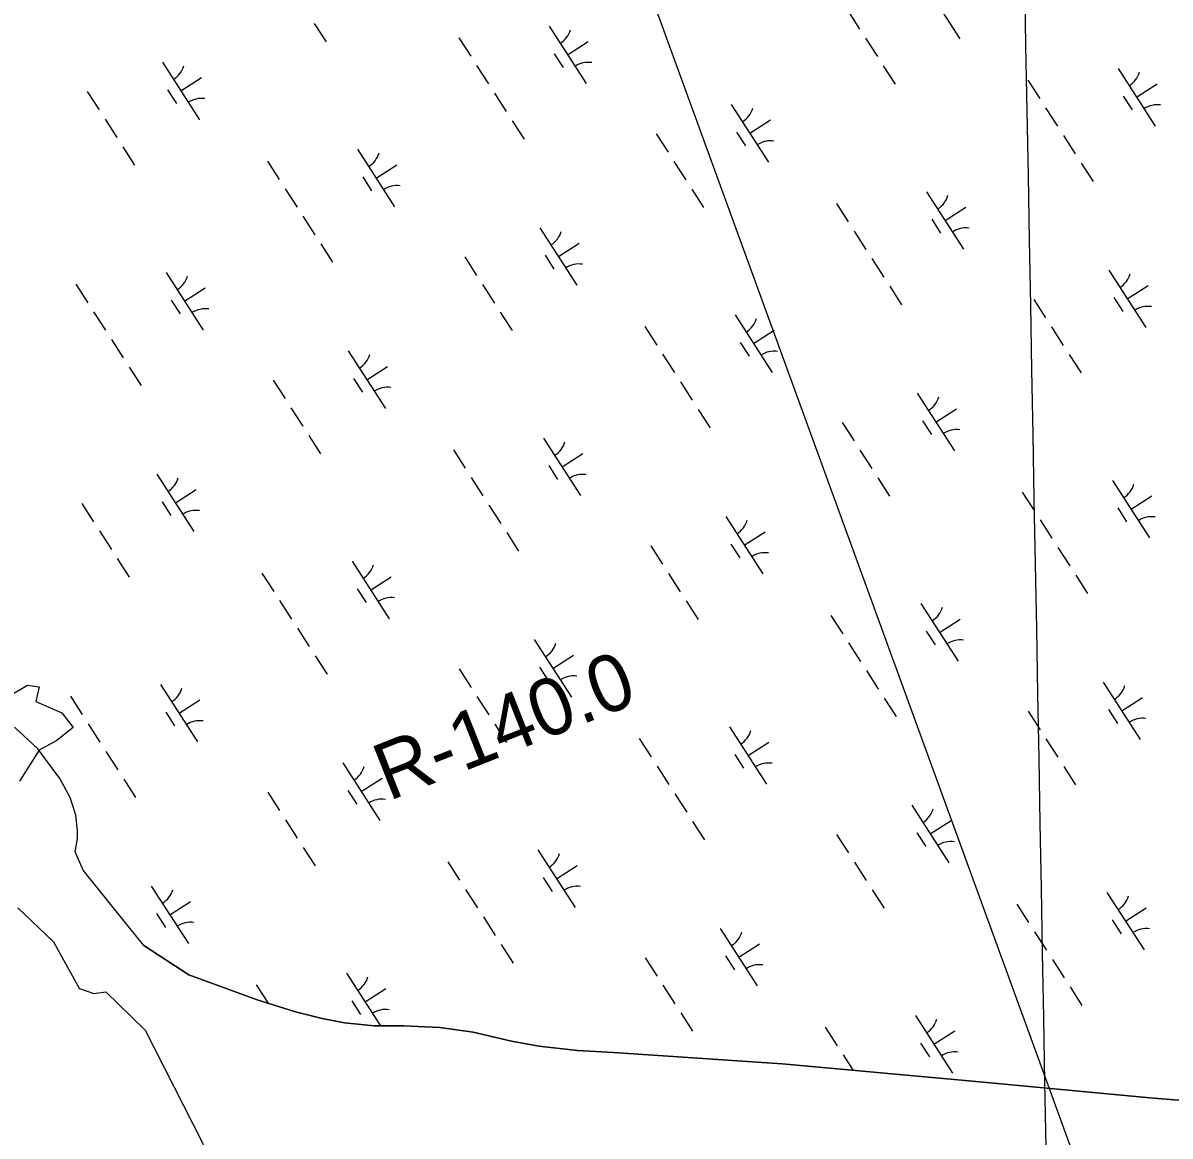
# Model space of a CAD drawing. Extents: x 3937982 to 3958556, y 219448 to 241894.
# Drawn here: x 3950723 to 3951560, y 226585 to 227398 of the extents above; entities that cross this region are included whole.
import ezdxf

# ---------------------------------------------------------------- set-up
doc = ezdxf.new("R2010")
doc.units = 0
for name, color, linetype in [('V-GRID-MAJR', 7, 'Continuous'), ('V-RIVR-EDGE', 7, 'Continuous'), ('V-RIVR-RANG-IDEN', 7, 'Continuous'), ('V-TOPO-SHOR', 7, 'Continuous'), ('V-UTIL-LINE', 7, 'Continuous'), ('V-WETL-SWMP', 7, 'Continuous')]:
    doc.layers.add(name, color=color, linetype=linetype)

msp = doc.modelspace()

# ---------------------------------------------------------------- linework, layer by layer
at = {"layer": 'V-GRID-MAJR'}
msp.add_spline([(3951546.997, 222374.883), (3951510.765, 224351.731), (3951399.696, 230411.652), (3951288.627, 236471.56), (3951286.871, 236567.353)], degree=3, dxfattribs=at)
at = {"layer": 'V-RIVR-EDGE'}
for points in [[(3950711.808, 226906.187), (3950726.055, 226914.497), (3950734.365, 226913.31), (3950731.991, 226902.625), (3950750.986, 226894.315), (3950759.297, 226883.63), (3950747.424, 226874.132), (3950734.365, 226867.009), (3950720.119, 226844.452)], [(3950718.931, 226751.849), (3950745.05, 226726.918), (3950764.045, 226692.489)], [(3950763.914, 226692.783), (3950774.486, 226689.109), (3950783.161, 226690.444), (3950811.858, 226662.414), (3950853.903, 226579.66), (3950860.576, 226552.298), (3950872.589, 226514.925), (3950913.966, 226447.521), (3950937.324, 226410.815), (3950952.674, 226373.442), (3950964.686, 226344.078), (3950977.367, 226312.712), (3950987.377, 226267.998), (3951005.396, 226236.631), (3951014.739, 226212.105), (3951013.738, 226210.27)]]:
    msp.add_lwpolyline(points, dxfattribs=at)
at = {"layer": 'V-TOPO-SHOR'}
msp.add_lwpolyline([(3950811.031, 226724.177), (3950843.914, 226702.791), (3950893.678, 226684.624), (3950921.81, 226675.69), (3950941.075, 226670.863), (3950957.473, 226667.84), (3950979.063, 226665.626), (3951000.643, 226665.493), (3951027.169, 226664.348), (3951051.368, 226660.85), (3951079.485, 226654.258), (3951099.525, 226650.735), (3951127.621, 226647.52), (3951153.889, 226646.115), (3951277.17, 226637.739), (3951413.475, 226625.279), (3951548.479, 226612.812), (3951710.785, 226599.726)], dxfattribs=at)
at = {"layer": 'V-UTIL-LINE'}
msp.add_lwpolyline([(3950785.675, 228505.622), (3951648.465, 226135.699)], dxfattribs=at)
at = {"layer": 'V-WETL-SWMP'}
for p, q in [((3951379.889, 227428.887), (3951406.951, 227386.844)), ((3951325.023, 227407.49), (3951333.683, 227394.036)), ((3950935.44, 227398.087), (3950944.1, 227384.634)), ((3951106.892, 227396.156), (3951133.955, 227354.113)), ((3951041.027, 227387.561), (3951049.687, 227374.107)), ((3951338.013, 227387.309), (3951346.673, 227373.855)), ((3951120.423, 227375.134), (3951135.559, 227384.877)), ((3950824.459, 227369.817), (3950851.521, 227327.773)), ((3951110.688, 227376.003), (3951117.183, 227365.913)), ((3951054.017, 227367.38), (3951062.677, 227353.926)), ((3951351.003, 227367.128), (3951359.662, 227353.674)), ((3951522.455, 227365.197), (3951549.517, 227323.153)), ((3950837.99, 227348.795), (3950853.126, 227358.537)), ((3951456.59, 227356.602), (3951465.25, 227343.148)), ((3951535.986, 227344.175), (3951551.121, 227353.917)), ((3950769.593, 227348.419), (3950778.253, 227334.966)), ((3950828.255, 227349.664), (3950834.75, 227339.574)), ((3951067.007, 227347.199), (3951075.667, 227333.746)), ((3951526.251, 227345.044), (3951532.746, 227334.954)), ((3951240.022, 227338.857), (3951267.084, 227296.814)), ((3951469.58, 227336.421), (3951478.24, 227322.967)), ((3950782.583, 227328.239), (3950791.243, 227314.785)), ((3951253.553, 227317.836), (3951268.688, 227327.578)), ((3951079.997, 227327.019), (3951088.657, 227313.565)), ((3951185.155, 227317.46), (3951193.815, 227304.006)), ((3951243.818, 227318.705), (3951250.312, 227308.615)), ((3951482.569, 227316.24), (3951491.229, 227302.786)), ((3950795.573, 227308.058), (3950804.233, 227294.604)), ((3950967.025, 227306.126), (3950994.087, 227264.083)), ((3950901.16, 227297.531), (3950909.82, 227284.078)), ((3950980.556, 227285.105), (3950995.692, 227294.847)), ((3951198.145, 227297.279), (3951206.805, 227283.826)), ((3951495.559, 227296.059), (3951504.219, 227282.606)), ((3950970.821, 227285.974), (3950977.316, 227275.884)), ((3950914.15, 227277.351), (3950922.81, 227263.897)), ((3951211.135, 227277.099), (3951219.795, 227263.645)), ((3951382.587, 227275.167), (3951409.65, 227233.124)), ((3951316.722, 227266.572), (3951325.382, 227253.118)), ((3951396.119, 227254.146), (3951411.254, 227263.888)), ((3950927.14, 227257.17), (3950935.8, 227243.716)), ((3951386.383, 227255.015), (3951392.878, 227244.924)), ((3951100.154, 227248.828), (3951127.217, 227206.785)), ((3951329.712, 227246.391), (3951338.372, 227232.938)), ((3950940.13, 227236.989), (3950948.79, 227223.535)), ((3951113.685, 227227.806), (3951128.821, 227237.549)), ((3951045.288, 227227.431), (3951053.948, 227213.977)), ((3951103.95, 227228.675), (3951110.445, 227218.585)), ((3951342.702, 227226.211), (3951351.362, 227212.757)), ((3950827.158, 227216.097), (3950854.22, 227174.054)), ((3951515.717, 227217.869), (3951542.779, 227175.825)), ((3950761.293, 227207.502), (3950769.953, 227194.048)), ((3950840.689, 227195.075), (3950855.824, 227204.818)), ((3951058.278, 227207.25), (3951066.938, 227193.796)), ((3951355.692, 227206.03), (3951364.352, 227192.576)), ((3951529.248, 227196.847), (3951544.383, 227206.589)), ((3950830.954, 227195.944), (3950837.449, 227185.854)), ((3951460.851, 227196.471), (3951469.511, 227183.018)), ((3951519.513, 227197.716), (3951526.008, 227187.626)), ((3950774.283, 227187.321), (3950782.943, 227173.867)), ((3951071.268, 227187.069), (3951079.928, 227173.615)), ((3951242.72, 227185.138), (3951269.782, 227143.094)), ((3951176.855, 227176.543), (3951185.515, 227163.089)), ((3951256.251, 227164.116), (3951271.387, 227173.858)), ((3951473.84, 227176.291), (3951482.5, 227162.837)), ((3950787.273, 227167.14), (3950795.933, 227153.687)), ((3951246.516, 227164.985), (3951253.011, 227154.895)), ((3950960.287, 227158.798), (3950987.349, 227116.755)), ((3951189.845, 227156.362), (3951198.505, 227142.908)), ((3951486.83, 227156.11), (3951495.49, 227142.656)), ((3950800.262, 227146.96), (3950808.922, 227133.506)), ((3950973.818, 227137.777), (3950988.954, 227147.519)), ((3950905.421, 227137.401), (3950914.081, 227123.947)), ((3950964.083, 227138.646), (3950970.578, 227128.556)), ((3951202.835, 227136.181), (3951211.495, 227122.727)), ((3951375.849, 227127.839), (3951402.912, 227085.796)), ((3950918.411, 227117.22), (3950927.071, 227103.767)), ((3951215.825, 227116), (3951224.485, 227102.547)), ((3951389.381, 227106.817), (3951404.516, 227116.56)), ((3951320.983, 227106.442), (3951329.643, 227092.988)), ((3951379.645, 227107.687), (3951386.14, 227097.596)), ((3950931.401, 227097.04), (3950940.061, 227083.586)), ((3951102.853, 227095.108), (3951129.915, 227053.065)), ((3951036.988, 227086.513), (3951045.648, 227073.059)), ((3951333.973, 227086.261), (3951342.633, 227072.807)), ((3951116.384, 227074.087), (3951131.52, 227083.829)), ((3950820.42, 227068.769), (3950847.482, 227026.726)), ((3951106.649, 227074.956), (3951113.144, 227064.865)), ((3951049.978, 227066.332), (3951058.638, 227052.879)), ((3951346.963, 227066.08), (3951355.623, 227052.627)), ((3951518.415, 227064.149), (3951545.478, 227022.106)), ((3950833.951, 227047.747), (3950849.086, 227057.49)), ((3951452.55, 227055.554), (3951461.21, 227042.1)), ((3951531.946, 227043.127), (3951547.082, 227052.87)), ((3950765.554, 227047.372), (3950774.214, 227033.918)), ((3950824.216, 227048.616), (3950830.711, 227038.526)), ((3951062.968, 227046.152), (3951071.628, 227032.698)), ((3951522.211, 227043.996), (3951528.706, 227033.906)), ((3951235.982, 227037.81), (3951263.044, 226995.766)), ((3951465.54, 227035.373), (3951474.2, 227021.919)), ((3950778.544, 227027.191), (3950787.204, 227013.737)), ((3951075.958, 227025.971), (3951084.618, 227012.517)), ((3951249.513, 227016.788), (3951264.649, 227026.53)), ((3951239.778, 227017.657), (3951246.273, 227007.567)), ((3951181.116, 227016.412), (3951189.776, 227002.959)), ((3951478.53, 227015.192), (3951487.19, 227001.739)), ((3950791.533, 227007.01), (3950800.193, 226993.556)), ((3950962.986, 227005.079), (3950990.048, 226963.035)), ((3950897.121, 226996.484), (3950905.781, 226983.03)), ((3950976.517, 226984.057), (3950991.652, 226993.799)), ((3951194.106, 226996.232), (3951202.766, 226982.778)), ((3951491.52, 226995.012), (3951500.18, 226981.558)), ((3950966.782, 226984.926), (3950973.277, 226974.836)), ((3950910.111, 226976.303), (3950918.77, 226962.849)), ((3951207.096, 226976.051), (3951215.756, 226962.597)), ((3951378.548, 226974.119), (3951405.61, 226932.076)), ((3951312.683, 226965.524), (3951321.343, 226952.071)), ((3951392.079, 226953.098), (3951407.215, 226962.84)), ((3950923.1, 226956.122), (3950931.76, 226942.668)), ((3951382.344, 226953.967), (3951388.839, 226943.877)), ((3951096.115, 226947.78), (3951123.177, 226905.737)), ((3951325.673, 226945.344), (3951334.333, 226931.89)), ((3950936.09, 226935.941), (3950944.75, 226922.488)), ((3951109.646, 226926.758), (3951124.782, 226936.501)), ((3951041.249, 226926.383), (3951049.909, 226912.929)), ((3951099.911, 226927.628), (3951106.406, 226917.537)), ((3951338.663, 226925.163), (3951347.323, 226911.709)), ((3951511.677, 226916.821), (3951538.74, 226874.778)), ((3950823.118, 226915.049), (3950850.181, 226873.006)), ((3950757.253, 226906.454), (3950765.913, 226893)), ((3950836.649, 226894.028), (3950851.785, 226903.77)), ((3951054.239, 226906.202), (3951062.899, 226892.748)), ((3951351.653, 226904.982), (3951360.313, 226891.528)), ((3951525.208, 226895.799), (3951540.344, 226905.542)), ((3950826.914, 226894.897), (3950833.409, 226884.806)), ((3951456.811, 226895.424), (3951465.471, 226881.97)), ((3951515.473, 226896.668), (3951521.968, 226886.578)), ((3950770.243, 226886.273), (3950778.903, 226872.82)), ((3951067.229, 226886.021), (3951075.889, 226872.568)), ((3951238.681, 226884.09), (3951265.743, 226842.047)), ((3951172.816, 226875.495), (3951181.476, 226862.041)), ((3951469.801, 226875.243), (3951478.461, 226861.789)), ((3951252.212, 226863.068), (3951267.347, 226872.811)), ((3950783.233, 226866.093), (3950791.893, 226852.639)), ((3951242.477, 226863.937), (3951248.972, 226853.847)), ((3950956.248, 226857.751), (3950983.31, 226815.707)), ((3951185.806, 226855.314), (3951194.466, 226841.86)), ((3951482.791, 226855.062), (3951491.451, 226841.608)), ((3950796.223, 226845.912), (3950804.883, 226832.458)), ((3950969.779, 226836.729), (3950984.914, 226846.471)), ((3950901.382, 226836.353), (3950910.041, 226822.9)), ((3950960.044, 226837.598), (3950966.539, 226827.508)), ((3951198.796, 226835.133), (3951207.455, 226821.68)), ((3951371.81, 226826.791), (3951398.872, 226784.748)), ((3950914.371, 226816.173), (3950923.031, 226802.719)), ((3951211.785, 226814.953), (3951220.445, 226801.499)), ((3951385.341, 226805.77), (3951400.477, 226815.512)), ((3951316.944, 226805.394), (3951325.604, 226791.94)), ((3951375.606, 226806.639), (3951382.101, 226796.549)), ((3950927.361, 226795.992), (3950936.021, 226782.538)), ((3951098.813, 226794.06), (3951125.876, 226752.017)), ((3951032.948, 226785.465), (3951041.608, 226772.012)), ((3951112.345, 226773.039), (3951127.48, 226782.781)), ((3951329.934, 226785.213), (3951338.594, 226771.76)), ((3950816.38, 226767.721), (3950843.443, 226725.678)), ((3951102.609, 226773.908), (3951109.104, 226763.818)), ((3951045.938, 226765.285), (3951054.598, 226751.831)), ((3951342.924, 226765.033), (3951351.584, 226751.579)), ((3951514.376, 226763.101), (3951541.438, 226721.058)), ((3950829.911, 226746.699), (3950845.047, 226756.442)), ((3951448.511, 226754.506), (3951457.171, 226741.052)), ((3951527.907, 226742.08), (3951543.043, 226751.822)), ((3950820.176, 226747.569), (3950826.671, 226737.478)), ((3951058.928, 226745.104), (3951067.588, 226731.65)), ((3951518.172, 226742.949), (3951524.667, 226732.858)), ((3951231.943, 226736.762), (3951259.005, 226694.719)), ((3951461.501, 226734.325), (3951470.161, 226720.872)), ((3951071.918, 226724.923), (3951080.578, 226711.469)), ((3951245.474, 226715.74), (3951260.609, 226725.483)), ((3951235.739, 226716.609), (3951242.234, 226706.519)), ((3951177.077, 226715.365), (3951185.737, 226701.911)), ((3951474.491, 226714.145), (3951483.151, 226700.691)), ((3950958.946, 226704.031), (3950983.684, 226665.598)), ((3950893.081, 226695.436), (3950901.675, 226682.084)), ((3950972.477, 226683.009), (3950987.613, 226692.752)), ((3951190.067, 226695.184), (3951198.726, 226681.73)), ((3951487.481, 226693.964), (3951496.14, 226680.51)), ((3950962.742, 226683.878), (3950969.237, 226673.788)), ((3951203.056, 226675.003), (3951211.716, 226661.549)), ((3951374.509, 226673.072), (3951401.571, 226631.028)), ((3951308.644, 226664.477), (3951317.304, 226651.023)), ((3951388.04, 226652.05), (3951403.175, 226661.792)), ((3951378.305, 226652.919), (3951384.8, 226642.829)), ((3951321.633, 226644.296), (3951328.898, 226633.01))]:
    msp.add_line(p, q, dxfattribs=at)
msp.add_lwpolyline([(3951710.786, 226599.725), (3951548.479, 226612.812), (3951413.474, 226625.279), (3951277.17, 226637.738), (3951153.888, 226646.114), (3951127.621, 226647.52), (3951099.524, 226650.735), (3951079.485, 226654.257), (3951051.368, 226660.851), (3951027.169, 226664.349), (3951000.644, 226665.493), (3950979.064, 226665.627), (3950957.473, 226667.84), (3950941.076, 226670.863), (3950921.809, 226675.69), (3950893.678, 226684.624), (3950843.914, 226702.791), (3950811.031, 226724.177), (3950794.6, 226744.512), (3950766.582, 226779.203), (3950760.693, 226792.782), (3950762.594, 226802.507), (3950762.569, 226808.337), (3950761.354, 226819.604), (3950757.024, 226832.412), (3950749.578, 226846.373), (3950733.548, 226868.07), (3950716.377, 226883.932)], dxfattribs=at)
for centre, start, end in [((3951105.673, 227398.489), 301.99668, 343.540338), ((3951135.573, 227352.037), 81.996677, 123.540335), ((3950823.24, 227372.149), 301.99668, 343.540338), ((3951521.235, 227367.529), 301.99668, 343.540338), ((3950853.14, 227325.698), 81.996677, 123.540335), ((3951238.802, 227341.19), 301.99668, 343.540338), ((3951551.135, 227321.078), 81.996677, 123.540335), ((3951268.702, 227294.738), 81.996677, 123.540335), ((3950965.806, 227308.459), 301.99668, 343.540338), ((3950995.706, 227262.007), 81.996677, 123.540335), ((3951381.368, 227277.5), 301.99668, 343.540338), ((3951098.935, 227251.161), 301.99668, 343.540338), ((3951411.268, 227231.048), 81.996677, 123.540335), ((3951128.835, 227204.709), 81.996677, 123.540335), ((3950825.939, 227218.43), 301.99668, 343.540338), ((3951514.497, 227220.201), 301.99668, 343.540338), ((3950855.839, 227171.978), 81.996677, 123.540335), ((3951544.397, 227173.75), 81.996677, 123.540335), ((3951241.501, 227187.47), 301.99668, 343.540338), ((3950959.068, 227161.131), 301.99668, 343.540338), ((3951271.401, 227141.019), 81.996677, 123.540335), ((3950988.968, 227114.679), 81.996677, 123.540335), ((3951374.63, 227130.172), 301.99668, 343.540338), ((3951404.53, 227083.72), 81.996677, 123.540335), ((3951101.634, 227097.441), 301.99668, 343.540338), ((3951131.534, 227050.989), 81.996677, 123.540335), ((3950819.201, 227071.102), 301.99668, 343.540338), ((3951517.196, 227066.482), 301.99668, 343.540338), ((3950849.101, 227024.65), 81.996677, 123.540335), ((3951234.763, 227040.142), 301.99668, 343.540338), ((3951547.096, 227020.03), 81.996677, 123.540335), ((3951264.663, 226993.691), 81.996677, 123.540335), ((3950961.766, 227007.411), 301.99668, 343.540338), ((3950991.666, 226960.96), 81.996677, 123.540335), ((3951377.329, 226976.452), 301.99668, 343.540338), ((3951094.896, 226950.113), 301.99668, 343.540338), ((3951407.229, 226930), 81.996677, 123.540335), ((3951124.796, 226903.661), 81.996677, 123.540335), ((3950821.899, 226917.382), 301.99668, 343.540338), ((3951510.458, 226919.154), 301.99668, 343.540338), ((3950851.799, 226870.93), 81.996677, 123.540335), ((3951540.358, 226872.702), 81.996677, 123.540335), ((3951237.461, 226886.423), 301.99668, 343.540338), ((3950955.028, 226860.083), 301.99668, 343.540338), ((3951267.362, 226839.971), 81.996677, 123.540335), ((3950984.928, 226813.632), 81.996677, 123.540335), ((3951370.591, 226829.124), 301.99668, 343.540338), ((3951400.491, 226782.672), 81.996677, 123.540335), ((3951097.594, 226796.393), 301.99668, 343.540338), ((3951127.494, 226749.941), 81.996677, 123.540335), ((3950815.161, 226770.054), 301.99668, 343.540338), ((3951513.157, 226765.434), 301.99668, 343.540338), ((3950845.061, 226723.602), 81.996677, 123.540335), ((3951230.723, 226739.095), 301.99668, 343.540338), ((3951543.057, 226718.982), 81.996677, 123.540335), ((3951260.623, 226692.643), 81.996677, 123.540335), ((3950957.727, 226706.364), 301.99668, 343.540338), ((3950987.627, 226659.912), 81.996677, 123.540335), ((3951373.289, 226675.404), 301.99668, 343.540338), ((3951403.189, 226628.953), 81.996677, 123.540335)]:
    msp.add_arc(centre, 17.623, start, end, dxfattribs=at)

# ---------------------------------------------------------------- texts
at = {"layer": 'V-RIVR-RANG-IDEN'}
msp.add_text('R-140.0', height=41.5, rotation=21.606405, dxfattribs=at).set_placement((3950989.687, 226829.614))

doc.saveas('drawing.dxf')
